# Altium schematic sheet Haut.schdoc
size 584 x 305 mm; Symbol: Drawing-Symbol_A4; @Project Name: Assisant vocal; @Page Count: 1; @Update Date: 2026-05-13; @Create Date: 2026-02-09; @Schematic Name: Dessus; @Page No: 1; @Page Name: Haut; Company: EasyEDA.com; Version: V1.0; Page Size: A4; @Create Time: 10:11:12; @Update Time: 18:02:13; Border: 1; Width: 2300; Height: 1200; Region Start: 1; X Region Count: 6; Y Region Count: 4; Blade Width: 10; Title Block Position: 3; @Board Name: Dessus; Device: Drawing-Symbol_A4
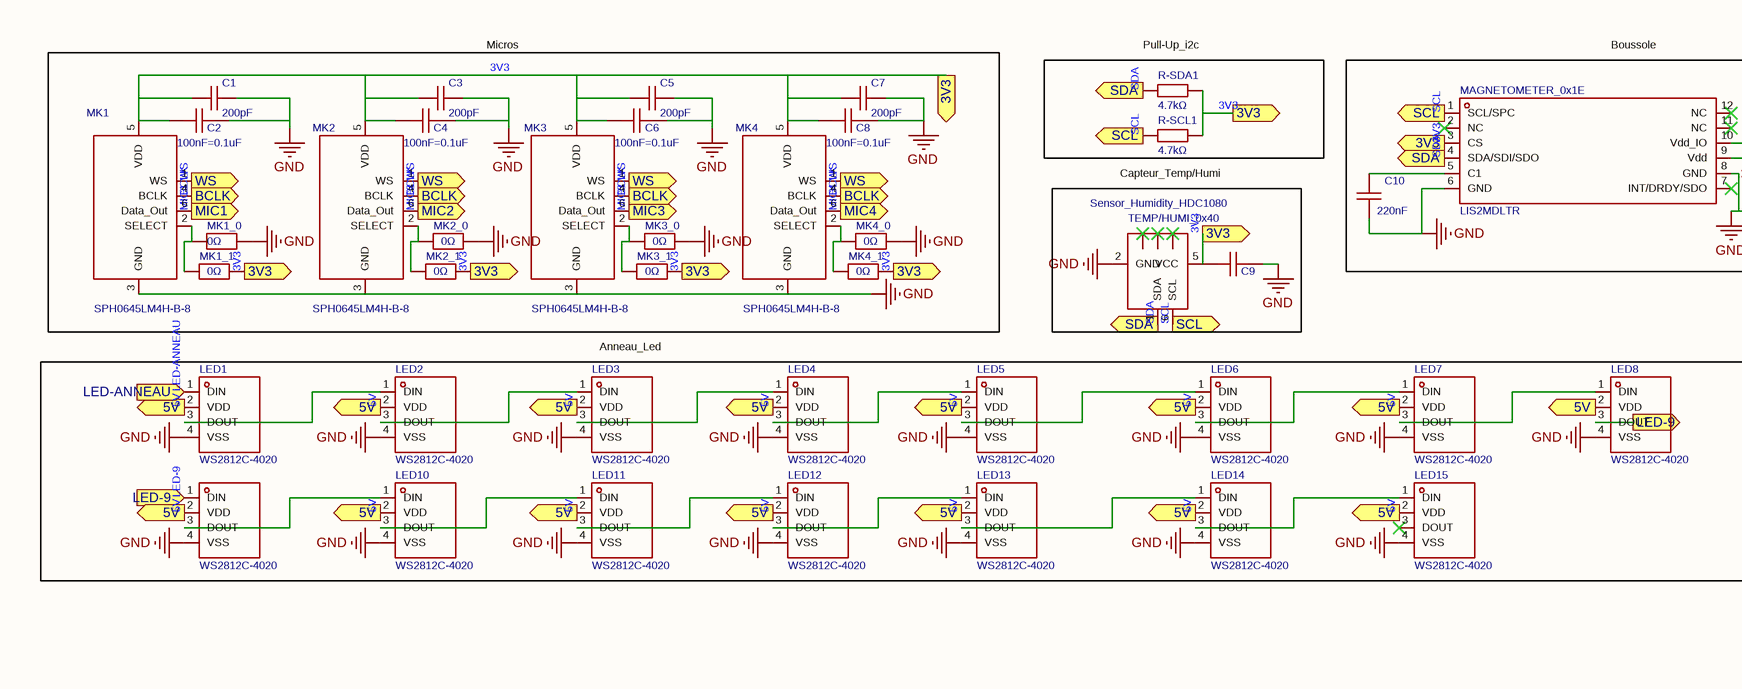
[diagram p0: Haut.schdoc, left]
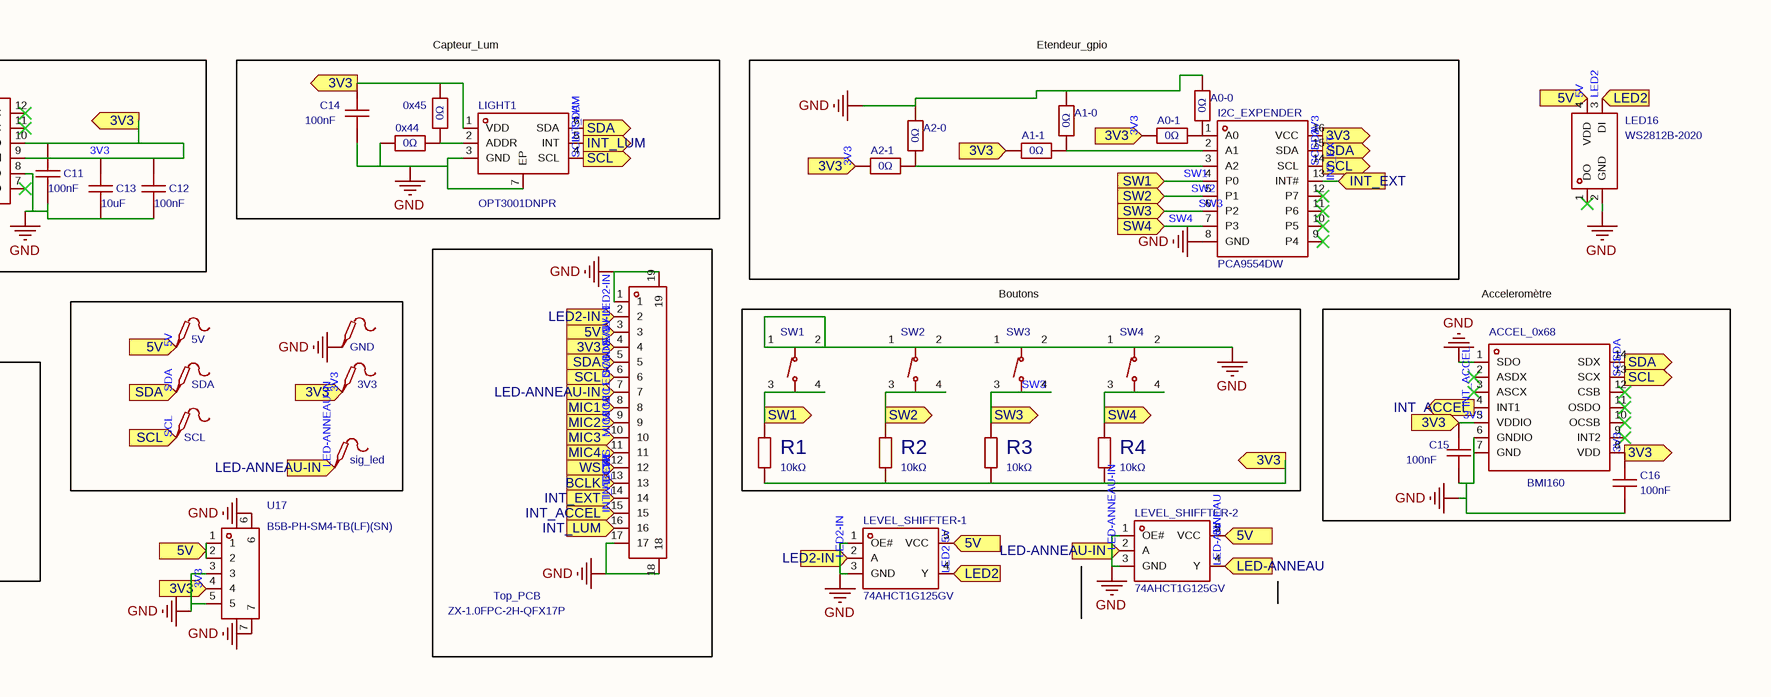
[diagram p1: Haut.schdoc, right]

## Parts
0x44  0Ω  [R0402]
0x45  0Ω  [R0402]
3V3  (no value)  [Test-Point-0.5mm]
5V  (no value)  [Test-Point-0.5mm]
A0-0  0Ω  [R0402]
A0-1  0Ω  [R0402]
A1-0  0Ω  [R0402]
A1-1  0Ω  [R0402]
A2-0  0Ω  [R0402]
A2-1  0Ω  [R0402]
ACCEL_0x68  BMI160  [LGA-14_L3.0-W2.5-P0.50-BL]
C1  200pF  [C0603]
C2  100nF=0.1uF  [C0603]
C3  200pF  [C0603]
C4  100nF=0.1uF  [C0603]
C5  200pF  [C0603]
C6  100nF=0.1uF  [C0603]
C7  200pF  [C0603]
C8  100nF=0.1uF  [C0603]
C9  CC0603KRX7R9BB104  [C0603]  (value not drawn)
C10  220nF  [C0603]
C11  100nF  [C0603]
C12  100nF  [C0603]
C13  10uF  [C0603]
C14  100nF  [C0603]
C15  100nF  [C0603]
C16  100nF  [C0603]
GND  (no value)  [Test-Point-0.5mm]
I2C_EXPENDER  PCA9554DW  [SOIC-16_L10.3-W7.5-P1.27-LS10.3-BL]
LED1  WS2812C-4020  [LED-SMD_4P-L4.0-W1.7-R]
LED2  WS2812C-4020  [LED-SMD_4P-L4.0-W1.7-R]
LED3  WS2812C-4020  [LED-SMD_4P-L4.0-W1.7-R]
LED4  WS2812C-4020  [LED-SMD_4P-L4.0-W1.7-R]
LED5  WS2812C-4020  [LED-SMD_4P-L4.0-W1.7-R]
LED6  WS2812C-4020  [LED-SMD_4P-L4.0-W1.7-R]
LED7  WS2812C-4020  [LED-SMD_4P-L4.0-W1.7-R]
LED8  WS2812C-4020  [LED-SMD_4P-L4.0-W1.7-R]
LED9  WS2812C-4020  [LED-SMD_4P-L4.0-W1.7-R]
LED10  WS2812C-4020  [LED-SMD_4P-L4.0-W1.7-R]
LED11  WS2812C-4020  [LED-SMD_4P-L4.0-W1.7-R]
LED12  WS2812C-4020  [LED-SMD_4P-L4.0-W1.7-R]
LED13  WS2812C-4020  [LED-SMD_4P-L4.0-W1.7-R]
LED14  WS2812C-4020  [LED-SMD_4P-L4.0-W1.7-R]
LED15  WS2812C-4020  [LED-SMD_4P-L4.0-W1.7-R]
LED16  WS2812B-2020  [LED-SMD_4P-L2.0-W2.0-TL_WS2812B-2020]
LEVEL_SHIFFTER-1  74AHCT1G125GV  [SOT-23-5_L3.0-W1.7-P0.95-LS2.8-BL]
LEVEL_SHIFFTER-2  74AHCT1G125GV  [SOT-23-5_L3.0-W1.7-P0.95-LS2.8-BL]
LIGHT1  OPT3001DNPR  [USON6_L2.1-W2.1-P0.65-BL-EP]
MAGNETOMETER_0x1E  LIS2MDLTR  [VLGA-12_L2.0-W2.0-P0.50-BL]
MK1  SPH0645LM4H-B-8  [MIC-SMD_6P-L3.5-W2.7-P0.90-BL]
MK1_0  0Ω  [R0402]
MK1_1  0Ω  [R0402]
MK2  SPH0645LM4H-B-8  [MIC-SMD_6P-L3.5-W2.7-P0.90-BL]
MK2_0  0Ω  [R0402]
MK2_1  0Ω  [R0402]
MK3  SPH0645LM4H-B-8  [MIC-SMD_6P-L3.5-W2.7-P0.90-BL]
MK3_0  0Ω  [R0402]
MK3_1  0Ω  [R0402]
MK4  SPH0645LM4H-B-8  [MIC-SMD_6P-L3.5-W2.7-P0.90-BL]
MK4_0  0Ω  [R0402]
MK4_1  0Ω  [R0402]
R1  10kΩ  [R0603]
R2  10kΩ  [R0603]
R3  10kΩ  [R0603]
R4  10kΩ  [R0603]
R-SCL1  4.7kΩ  [R0603]
R-SDA1  4.7kΩ  [R0603]
SCL  (no value)  [Test-Point-0.5mm]
SDA  (no value)  [Test-Point-0.5mm]
sig_led  sig_led  [Test-Point-0.5mm]  (value not drawn)
SW1  TS-1187A-B-A-B  [SW-SMD_4P-L5.1-W5.1-P3.70-LS6.5-TL_H1.5]  (value not drawn)
SW2  TS-1187A-B-A-B  [SW-SMD_4P-L5.1-W5.1-P3.70-LS6.5-TL_H1.5]  (value not drawn)
SW3  TS-1187A-B-A-B  [SW-SMD_4P-L5.1-W5.1-P3.70-LS6.5-TL_H1.5]  (value not drawn)
SW4  TS-1187A-B-A-B  [SW-SMD_4P-L5.1-W5.1-P3.70-LS6.5-TL_H1.5]  (value not drawn)
TEMP/HUMI_0x40  Sensor_Humidity_HDC1080  [Package_SON:Texas_PWSON-N6]
Top_PCB  ZX-1.0FPC-2H-QFX17P  [FPC-SMD_17P-P1.00_ZX-1.0FPC-2H-QFX17P]
U17  B5B-PH-SM4-TB(LF)(SN)  [CONN-SMD_5P-P2.00_B6B-PH-SM4-TB-LF-SN]

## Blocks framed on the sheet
Micros: C1-C8 MK1 MK1_0 MK1_1 MK2 MK2_0 MK2_1 MK3 MK3_0 MK3_1 MK4 MK4_0 MK4_1
Pull-Up_i2c: R-SCL1 R-SDA1
Boussole: C10-C13 MAGNETOMETER_0x1E
Capteur_Lum: 0x44 0x45 C14 LIGHT1
Etendeur_gpio: A0-0 A0-1 A1-0 A1-1 A2-0 A2-1 I2C_EXPENDER
Capteur_Temp/Humi: C9 TEMP/HUMI_0x40
Boutons: R1-R4 SW1-SW4
Acceleromètre: ACCEL_0x68 C15 C16
Anneau_Led: LED1-LED15

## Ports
3V3 (in), 3V3 (out), 5V (in), 5V (out), BCLK (in), BCLK (out), INT_ACCEL (in), INT_ACCEL (out), INT_EXT (in), INT_LUM (in), INT_LUM (out), LED2 (in), LED2-IN (in), LED-9 (in), LED-9 (out), LED-ANNEAU (in), LED-ANNEAU-IN (in), MIC1 (in), MIC1 (out), MIC2 (in), MIC2 (out), MIC3 (in), MIC3 (out), MIC4 (in), MIC4 (out), SCL (in), SCL (out), SDA (in), SDA (out), SW1 (in), SW1 (out), SW2 (in), SW2 (out), SW3 (in), SW3 (out), SW4 (in), SW4 (out), WS (in), WS (out)

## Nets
GND: 0x44.1 A0-0.1 A1-0.2 A2-0.2 ACCEL_0x68.1(SDO) ACCEL_0x68.6(GNDIO) ACCEL_0x68.7(GND) C1.2 C2.2 C3.2 C4.2 C5.2 C6.2 C7.2 C8.2 C9.2 C10.1 C11.1 C12.1 C13.1 C14.1 C15.1 C16.1 GND.1 I2C_EXPENDER.8(GND) LED1.4(VSS) LED2.4(VSS) LED3.4(VSS) LED4.4(VSS) LED5.4(VSS) LED6.4(VSS) LED7.4(VSS) LED8.4(VSS) LED9.4(VSS) LED10.4(VSS) LED11.4(VSS) LED12.4(VSS) LED13.4(VSS) LED14.4(VSS) LED15.4(VSS) LED16.2(GND) LEVEL_SHIFFTER-1.1(OE#) LEVEL_SHIFFTER-1.3(GND) LEVEL_SHIFFTER-2.1(OE#) LEVEL_SHIFFTER-2.3(GND) LIGHT1.3(GND) LIGHT1.7(EP) MAGNETOMETER_0x1E.6(GND) MAGNETOMETER_0x1E.8(GND) MK1.3(GND) MK1_0.2 MK2.3(GND) MK2_0.2 MK3.3(GND) MK3_0.2 MK4.3(GND) MK4_0.2 SW1.1(A) SW1.2(B) SW2.1(A) SW2.2(B) SW3.1(A) SW3.2(B) SW4.1(A) SW4.2(B) TEMP/HUMI_0x40.2(GND) Top_PCB.1 Top_PCB.17 Top_PCB.18 Top_PCB.19 U17.3 U17.5 U17.6 U17.7
3V3: 0x45.2 3V3.1 A0-1.1 A1-1.1 A2-1.1 ACCEL_0x68.5(VDDIO) ACCEL_0x68.8(VDD) C1.1 C2.1 C3.1 C4.1 C5.1 C6.1 C7.1 C8.1 C9.1 C11.2 C12.2 C13.2 C14.2 C15.2 C16.2 I2C_EXPENDER.16(VCC) LIGHT1.1(VDD) MAGNETOMETER_0x1E.3(CS) MAGNETOMETER_0x1E.9(Vdd) MAGNETOMETER_0x1E.10(Vdd_IO) MK1.5(VDD) MK1_1.2 MK2.5(VDD) MK2_1.2 MK3.5(VDD) MK3_1.2 MK4.5(VDD) MK4_1.2 R1.1 R2.1 R3.1 R4.1 R-SCL1.2 R-SDA1.2 TEMP/HUMI_0x40.5(VCC) Top_PCB.4 U17.4 ; port 3V3
5V: 5V.1 LED1.2(VDD) LED2.2(VDD) LED3.2(VDD) LED4.2(VDD) LED5.2(VDD) LED6.2(VDD) LED7.2(VDD) LED8.2(VDD) LED9.2(VDD) LED10.2(VDD) LED11.2(VDD) LED12.2(VDD) LED13.2(VDD) LED14.2(VDD) LED15.2(VDD) LED16.4(VDD) LEVEL_SHIFFTER-1.5(VCC) LEVEL_SHIFFTER-2.5(VCC) Top_PCB.3 U17.1 U17.2 ; port 5V
BCLK: MK1.4(BCLK) MK2.4(BCLK) MK3.4(BCLK) MK4.4(BCLK) Top_PCB.13 ; port BCLK
INT_ACCEL: ACCEL_0x68.4(INT1) Top_PCB.15 ; port INT_ACCEL
INT_EXT: I2C_EXPENDER.13(INT#) Top_PCB.14 ; port INT_EXT
INT_LUM: LIGHT1.5(INT) Top_PCB.16 ; port INT_LUM
LED2: LED16.3(DI) LEVEL_SHIFFTER-1.4(Y) ; port LED2
LED2-IN: LEVEL_SHIFFTER-1.2(A) Top_PCB.2 ; port LED2-IN
LED-9: LED8.3(DOUT) LED9.1(DIN) ; port LED-9
LED-ANNEAU: LED1.1(DIN) LEVEL_SHIFFTER-2.4(Y) ; port LED-ANNEAU
LED-ANNEAU-IN: LEVEL_SHIFFTER-2.2(A) sig_led.1 Top_PCB.7 ; port LED-ANNEAU-IN
MIC1: MK1.6(Data_Out) Top_PCB.8 ; port MIC1
MIC2: MK2.6(Data_Out) Top_PCB.9 ; port MIC2
MIC3: MK3.6(Data_Out) Top_PCB.10 ; port MIC3
MIC4: MK4.6(Data_Out) Top_PCB.11 ; port MIC4
SCL: ACCEL_0x68.13(SCX) I2C_EXPENDER.14(SCL) LIGHT1.4(SCL) MAGNETOMETER_0x1E.1(SCL/SPC) R-SCL1.1 SCL.1 TEMP/HUMI_0x40.6(SCL) Top_PCB.6 ; port SCL
SDA: ACCEL_0x68.14(SDX) I2C_EXPENDER.15(SDA) LIGHT1.6(SDA) MAGNETOMETER_0x1E.4(SDA/SDI/SDO) R-SDA1.1 SDA.1 TEMP/HUMI_0x40.1(SDA) Top_PCB.5 ; port SDA
SW1: I2C_EXPENDER.4(P0) R1.2 SW1.3(C) SW1.4(D) ; port SW1
SW2: I2C_EXPENDER.5(P1) R2.2 SW2.3(C) SW2.4(D) ; port SW2
SW3: I2C_EXPENDER.6(P2) R3.2 SW3.3(C) SW3.4(D) ; port SW3
SW4: I2C_EXPENDER.7(P3) R4.2 SW4.3(C) SW4.4(D) ; port SW4
WS: MK1.1(WS) MK2.1(WS) MK3.1(WS) MK4.1(WS) Top_PCB.12 ; port WS
Net0x44_2: 0x44.2 0x45.1 LIGHT1.2(ADDR)
NetA0-0_2: A0-0.2 A0-1.2 I2C_EXPENDER.1(A0)
NetA1-0_1: A1-0.1 A1-1.2 I2C_EXPENDER.2(A1)
NetA2-0_1: A2-0.1 A2-1.2 I2C_EXPENDER.3(A2)
NetC10_2: C10.2 MAGNETOMETER_0x1E.5(C1)
NetLED1_3: LED1.3(DOUT) LED2.1(DIN)
NetLED2_3: LED2.3(DOUT) LED3.1(DIN)
NetLED3_3: LED3.3(DOUT) LED4.1(DIN)
NetLED4_3: LED4.3(DOUT) LED5.1(DIN)
NetLED5_3: LED5.3(DOUT) LED6.1(DIN)
NetLED6_3: LED6.3(DOUT) LED7.1(DIN)
NetLED7_3: LED7.3(DOUT) LED8.1(DIN)
NetLED9_3: LED9.3(DOUT) LED10.1(DIN)
NetLED10_3: LED10.3(DOUT) LED11.1(DIN)
NetLED11_3: LED11.3(DOUT) LED12.1(DIN)
NetLED12_3: LED12.3(DOUT) LED13.1(DIN)
NetLED13_3: LED13.3(DOUT) LED14.1(DIN)
NetLED14_3: LED14.3(DOUT) LED15.1(DIN)
NetMK1_2: MK1.2(SELECT) MK1_0.1 MK1_1.1
NetMK2_2: MK2.2(SELECT) MK2_0.1 MK2_1.1
NetMK3_2: MK3.2(SELECT) MK3_0.1 MK3_1.1
NetMK4_2: MK4.2(SELECT) MK4_0.1 MK4_1.1

Not connected (* = marked no-connect by the designer): ACCEL_0x68 2(ASDX)* 3(ASCX)* 9(INT2)* 10(OCSB)* 11(OSDO)* 12(CSB)*; I2C_EXPENDER 9(P4)* 10(P5)* 11(P6)* 12(P7)*; LED15 3(DOUT)*; LED16 1(DO)*; MAGNETOMETER_0x1E 2(NC)* 7(INT/DRDY/SDO)* 11(NC)* 12(NC)*; TEMP/HUMI_0x40 3(NC)* 4(NC)* 7(DAP)*

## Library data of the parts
0x44 0x45 A0-0 A0-1 A1-0 A1-1 A2-0 A2-1 MK1_0 MK1_1 MK2_0 MK2_1 MK3_0 MK3_1 MK4_0 MK4_1 = FRC0402P000 TS: Type:Thick Film Resistor Resistance:0Ω Tolerance:±5% Tolerance:±5% Power(Watts):62.5mW Voltage-Supply(Max):50V Operating Temperature:-55℃~+155℃ Operating Temperature:-55℃~+155℃; Manufacturer: FOJAN(富捷); AddInBom: yes; ModelId: efdecb7dae4442949d28eecaf748420f; ModelName: R0402_L1.0-W0.5-H0.4; ModelTransform: 39.37,19.685,0,0,0,0,0,0,0; Tolerance: ±5%; Power(Watts): 62.5mW; Voltage-Supply(Max): 50V
3V3 5V GND SCL SDA sig_led = Test-Point: Test Point 测试点; AddInBom: yes
ACCEL_0x68 = BMI160: Accelerometer Sensing Axis:X,Y,Z Acceleration Measurement Range (MAX):±16g Acceleration Measurement Range (MAX):±16g Gyroscope Sensing Axis:X,Y,Z Gyroscope Measurement Range (MAX):±2000dps Gyroscope Measurement Range (MAX):±2000dps Sensor Type:IMU Output; Manufacturer: Bosch(博世); AddInBom: yes; ModelId: ba71f3cdab504178a9a45bd067d2295b; ModelName: LGA-14_L2.5-W3.0-H0.9-P0.50; ModelTransform: 118.11,98.425,0,90,0,0,-0.0005,0,0; Accelerometer Sensing Axis: X,Y,Z; Acceleration Measurement Range (MAX): ±16g; Sensor Type: IMU; Output Bits: 16bit; Interface: I2C；SPI; Voltage - Supply: 1.71V~3.6V; Cache Size: 1KB; Standby Current: 10uA
C1 C3 C5 C7 = CC0603KRX7R9BB201: Capacitance:200pF Tolerance:±10% Tolerance:±10% Voltage Rating:50V Temperature Coefficient:X7R; Manufacturer: YAGEO(国巨); AddInBom: yes; ModelId: 624118aa3cc7497086c383c2d72e0852; ModelName: C0603_L1.6-W0.8-H0.8; ModelTransform: 62.992,31.496,0,0,0,0,0,0,0; Tolerance: ±10%; Voltage Rating: 50V; Temperature Coefficient: X7R
C2 C4 C6 C8 C11 C12 C15 C16 = CC0603KRX7R9BB104: Capacitance:100nF Tolerance:±10% Tolerance:±10% Voltage Rating:50V Temperature Coefficient:X7R; Manufacturer: YAGEO(国巨); AddInBom: yes; ModelId: 624118aa3cc7497086c383c2d72e0852; ModelName: C0603_L1.6-W0.8-H0.8; ModelTransform: 62.992,31.496,0,0,0,0,0,0,0; Tolerance: ±10%; Voltage Rating: 50V; Temperature Coefficient: X7R
C9 = CC0603KRX7R9BB104: Capacitance:100nF Tolerance:±10% Tolerance:±10% Voltage Rating:50V Temperature Coefficient:X7R; Manufacturer: YAGEO(国巨); Value: 100nF=0.1uF; AddInBom: yes; ModelId: 624118aa3cc7497086c383c2d72e0852; ModelName: C0603_L1.6-W0.8-H0.8; ModelTransform: 62.992,31.496,0,0,0,0,0,0,0; Tolerance: ±10%; Voltage Rating: 50V; Temperature Coefficient: X7R
C10 = CL10B224KB8NNNC: Capacitance:220nF Tolerance:±10% Tolerance:±10% Voltage Rating:50V Temperature Coefficient:X7R; Manufacturer: SAMSUNG(三星); AddInBom: yes; ModelId: 624118aa3cc7497086c383c2d72e0852; ModelName: C0603_L1.6-W0.8-H0.8; ModelTransform: 62.992,31.496,0,0,0,0,0,0,0; Tolerance: ±10%; Voltage Rating: 50V; Temperature Coefficient: X7R
C13 = CL10A106MQ8NNNC: Capacitance:10uF Tolerance:±20% Tolerance:±20% Voltage Rating:6.3V Temperature Coefficient:X5R; Manufacturer: SAMSUNG(三星); AddInBom: yes; ModelId: 624118aa3cc7497086c383c2d72e0852; ModelName: C0603_L1.6-W0.8-H0.8; ModelTransform: 62.992,31.496,0,0,0,0,0,0,0; Tolerance: ±20%; Voltage Rating: 6.3V; Temperature Coefficient: X5R
C14 = CC0603KRX7R5BB104: Capacitance:100nF Tolerance:±10% Tolerance:±10% Voltage Rated: Temperature Coefficient:; Manufacturer: YAGEO(国巨); AddInBom: yes; ModelId: 624118aa3cc7497086c383c2d72e0852; ModelName: C0603_L1.6-W0.8-H0.8; ModelTransform: 62.992,31.496,0,0,0,0,0,0,0; Tolerance: ±10%
I2C_EXPENDER = PCA9554DW: Interface:I2C；SMBus Number of I/O:8 Interrupt Output:Interrupt Output Output Type:- Voltage - Supply:2.3V~5.5V Voltage - Supply:2.3V~5.5V Current - Output Low(IOL):- Current - Output High(IOH):- Clock Frequency:400kHz Operating Temperature:-40℃~+85℃ Opera; Manufacturer: TI(德州仪器); AddInBom: yes; ModelId: 649b7cb6adae474980397c0a68e6a41c; ModelName: SOIC-16_L10.3-W7.5-H2.7-LS10.3-P1.27; ModelTransform: 405.511,409.68154,0,0,0,0,-0.0005,0,0; Number of I/O: 8; Clock Frequency: 400kHz
LED1-LED15 = WS2812C-4020: Wavelength:B:470nm~475nm；G:525nm~530nm；R:625nm~630nm Luminous Intensity:R:150mcd~200mcd；B:100mcd~150mcd；G:400mcd~600mcd Fixed-Frequency Pwm Mode:2kHz Data Transmission Rate:800Kbit/s Voltage - Supply:4.5V~5.5V Voltage - Supply:4.5V~5.5V Operating Temperat; Manufacturer: worldsemi; AddInBom: yes; ModelId: 5bbf1a6f37ee475883f871c477343486; ModelTransform: 157.48,66.929,0,0,0,0,0,20.945,0; Fixed-Frequency Pwm Mode: 2kHz
LED16 = WS2812B-2020: Wavelength:515.6nm；622.5nm；470.4nm Luminous Intensity:200mcd；160mcd；520mcd Fixed-Frequency Pwm Mode:- Data Transmission Rate:100KB/S Voltage - Supply:5V Voltage - Supply:5V Quiescent Current:- Lens Color:- ESD Withstand Voltage:- Installation method:op Vi; Manufacturer: worldsemi; AddInBom: yes; ModelId: 2073fdeeec114646a88cc45513eb03db; ModelName: LED-SMD_4P-L2.0-W2.0-H0.8-TL_WS2812B-2020; ModelTransform: 78.74,78.74,0,0,0,0,0.001,0.005,0; Voltage - Supply: 5V; Installation method: op View Mount
LEVEL_SHIFFTER-1 LEVEL_SHIFFTER-2 = 74AHCT1G125GV: Input type:- output type:Tri-State Voltage - Supply:4.5V~5.5V Voltage - Supply:4.5V~5.5V Number of Elements:1 Number of Bits per Element:1 Channel Type:Unidirectional Current - Output Low(IOL):8mA Current - Output High(IOH):8mA Logic Family:74AHCT Operati; Manufacturer: MDD(辰达半导体); AddInBom: yes; ModelId: 3168b22659ce4998ae232d44bb704e0a; ModelName: SOT-23-5_L2.9-W1.6-H1.1-LS2.8-P0.95; ModelTransform: 118.60433,114.173,0,90,0,0,0.0005,0.0005,0; Number of Elements: 1; Current - Output Low(IOL): 8mA; Logic Family: 74AHCT; Quiescent Current: 40uA; Propagation Delay: 1ns@4.5V
LIGHT1 = OPT3001DNPR: Manufacturer: TI(德州仪器); AddInBom: yes; ModelId: b16380ec364c4bb4a39a125d40a5814f; ModelName: USON-6_L2.0-W2.0-H0.7-P0.65; ModelTransform: 79.527,78.74,0,90,0,0,0.355,0.513,0
MAGNETOMETER_0x1E = LIS2MDLTR: Manufacturer: ST(意法半导体); AddInBom: yes; ModelId: b0008713ed0247d78d2774602adb0ecc; ModelTransform: 78.74,78.74,0,90,0,0,0,0,0
MK1-MK4 = SPH0645LM4H-B-8: Manufacturer: Knowles(楼氏); AddInBom: yes; ModelId: da30a433fdf74333be7c10328fb3f492; ModelTransform: 104.3305,137.795,0,90,0,0,3.197,-0.001,0
R1-R4 = 0603WAF1002T5E: Type:Thick Film Resistor Resistance:10kΩ Tolerance:±1% Tolerance:±1% Power(Watts):100mW Voltage-Supply(Max):75V Temperature Coefficient:±100ppm/℃ Temperature Coefficient:±100ppm/℃ Operating Temperature:-55℃~+155℃ Operating Temperature:-55℃~+155℃; Manufacturer: UNI-ROYAL(厚声); AddInBom: yes; ModelId: 112863783b5b41f1b5254f87eedc7932; ModelTransform: 31.8897,63.7794,0,90,0,0,0,0,0; Tolerance: ±1%; Power(Watts): 100mW; Voltage-Supply(Max): 75V
R-SCL1 R-SDA1 = RC0603FR-074K7L: Type:Thick Film Resistor Resistance:4.7kΩ Tolerance:±1% Tolerance:±1% Power(Watts):100mW Voltage-Supply(Max):75V Temperature Coefficient:±100ppm/℃ Temperature Coefficient:±100ppm/℃ Operating Temperature:-55℃~+155℃ Operating Temperature:-55℃~+155℃; Manufacturer: YAGEO(国巨); AddInBom: yes; ModelId: 112863783b5b41f1b5254f87eedc7932; ModelTransform: 31.8897,63.7794,0,90,0,0,0,0,0; Tolerance: ±1%; Power(Watts): 100mW; Voltage-Supply(Max): 75V
SW1-SW4 = TS-1187A-B-A-B: Circuit:SPST Actuator Style:Round Button Operating Force:1.6N Mounting Type:Surface Mount,Vertical Length:5.1mm Width:5.1mm Switch Height:1.5mm with Bracket:Without Bracket Contact Current:50mA Voltage Rating:12V Actuator/Cap Color:Gold With Lamp:No Life:; Manufacturer: XKB Connection(中国星坤); AddInBom: yes; ModelId: 297e93217c8a461096f3cf9cc3d4db3d; ModelTransform: 255.905,204.76337,0,0,0,0,0,0,0; Circuit: SPST; Operating Force: 1.6N; Switch Height: 1.5mm; Contact Current: 50mA; Voltage Rating: 12V; Actuator/Cap Color: Gold; With Lamp: No; Life: 100,000 Cycles
TEMP/HUMI_0x40 = Sensor_Humidity_HDC1080: AddInBom: yes; Value: HDC1080DMBR
Top_PCB = ZX-1.0FPC-2H-QFX17P: Locking Feature:Hinged Lid Contact Type:Bottom Contact Number of Contacts:17P Pitch:1mm Mounting Type:Surface Mount, Right Angle FFC, FCB Thickness:0.3mm FFC, FCB Thickness:0.3mm Height Above Board:2mm Contact Material:Copper alloy Contact Plating:Tin Ope; Manufacturer: Megastar(兆星); AddInBom: yes; ModelId: 937d878fdcf348138d9ffcb84035bd35; ModelTransform: 862.5967,236.22,0,0,0,0,-5.04,-44.941,0; Number of Contacts: 17P; Pitch: 1mm; FFC, FCB Thickness: 0.3mm; Rated Voltage (Max): 50V
U17 = B5B-PH-SM4-TB(LF)(SN): Pins Structure:1x5P Pitch:2mm Mounting Type:Surface Mount,Vertical Reference Series:PH Number of Pins:5P Number of Rows:1 Number of PINs Per Row:5 Row Spacing:- Current Rating:2A Contact Material:Copper Alloy Contact Plating:Tin Operating Temperature:-25℃; Manufacturer: JST; AddInBom: yes; ModelId: 42661aa5dd484b92a752559c239d11dd; ModelTransform: 551.18,295.275,0,0,0,0,0,3.425,0; Pins Structure: 1x5P; Pitch: 2mm; Reference Series: PH; Number of PINs Per Row: 5; Current Rating: 2A; Voltage Rating: 100V; Plastic Material: PA; Flame Retardant Rating: UL94V-0; Supplementary Features: Auxiliary Solder Pin; Z-Height of the Board: 6.6mm; X-Length of Bottom Edge on Board (Spacing Line): 13.95mm; Y-Width of Bottom Edge on Board: 7mm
